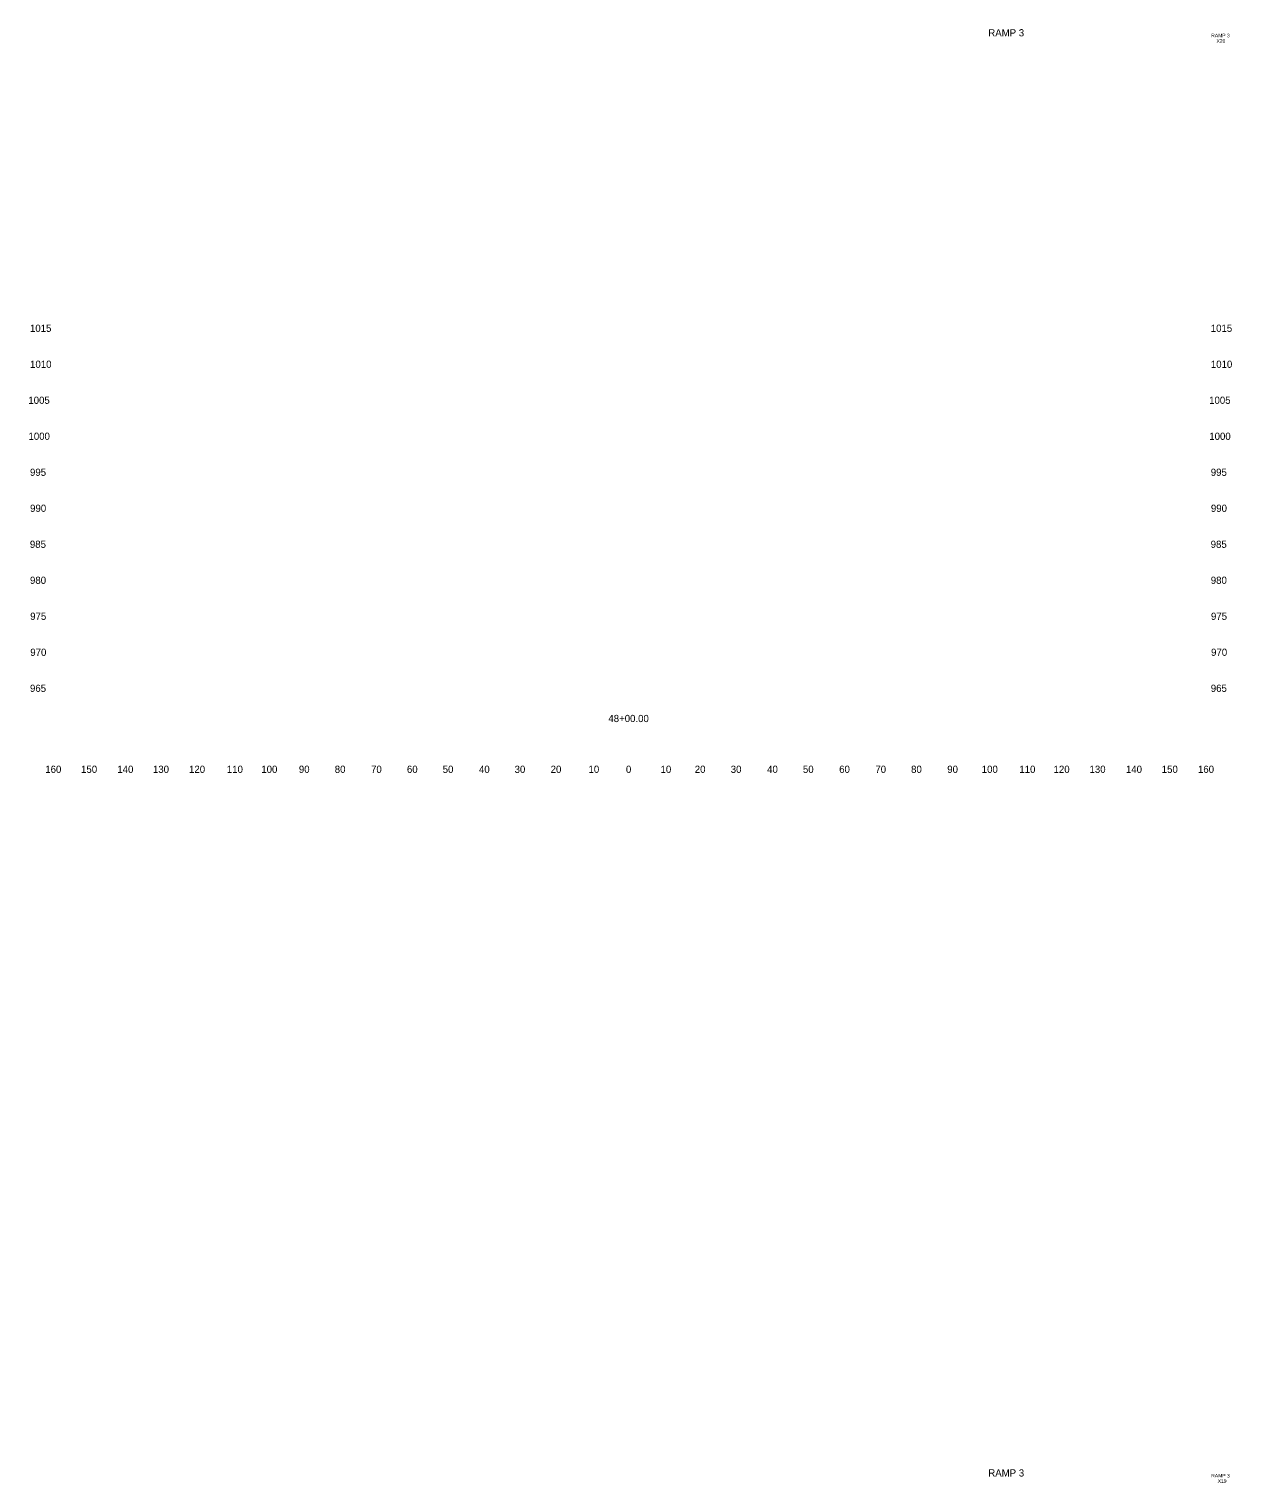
# Model space of a CAD drawing. Extents: x 4994 to 5843, y 4997 to 8804.
# Drawn here: x 5508.6 to 5842.5, y 8400.3 to 8804.1 of the extents above; entities that cross this region are included whole.
import ezdxf

# ---------------------------------------------------------------- set-up
doc = ezdxf.new("R2010")
doc.units = 0
for name, color, linetype in [('RD_SHT_ID', 7, 'Continuous'), ('RD_XS_TX_Offset', 7, 'Continuous'), ('RD_XS_TX_Station', 7, 'Continuous')]:
    doc.layers.add(name, color=color, linetype=linetype)

msp = doc.modelspace()

# ---------------------------------------------------------------- texts
at = {"layer": 'RD_SHT_ID'}
for s, height, p in [('RAMP 3', 2, (5774.89, 8802.06)), ('RAMP 3', 1, (5836.78, 8801.8)), ('X20', 1, (5838.25, 8800.3)), ('RAMP 3', 2, (5774.89, 8402.06)), ('RAMP 3', 1, (5836.78, 8401.8)), ('X19', 1, (5838.57, 8400.3))]:
    msp.add_text(s, height=height, dxfattribs=at).set_placement(p)
at = {"layer": 'RD_XS_TX_Offset'}
for s, p in [('1015', (5508.85, 8720)), ('1015', (5836.65, 8720)), ('1010', (5508.88, 8710)), ('1010', (5836.68, 8710)), ('1005', (5508.4, 8700)), ('1005', (5836.2, 8700)), ('1000', (5508.44, 8690)), ('1000', (5836.24, 8690)), ('995', (5508.86, 8680)), ('995', (5836.66, 8680)), ('990', (5508.89, 8670)), ('990', (5836.69, 8670)), ('985', (5508.83, 8660)), ('985', (5836.63, 8660)), ('980', (5508.86, 8650)), ('980', (5836.66, 8650)), ('975', (5508.91, 8640)), ('975', (5836.71, 8640)), ('970', (5508.94, 8630)), ('970', (5836.74, 8630)), ('965', (5508.86, 8620)), ('965', (5836.66, 8620)), ('160', (5513.1, 8597.5)), ('150', (5523.04, 8597.5)), ('140', (5533.1, 8597.5)), ('130', (5542.99, 8597.5)), ('120', (5553.01, 8597.5)), ('110', (5563.51, 8597.5)), ('100', (5573.07, 8597.5)), ('90', (5583.5, 8597.5)), ('80', (5593.46, 8597.5)), ('70', (5603.54, 8597.5)), ('60', (5613.5, 8597.5)), ('50', (5623.43, 8597.5)), ('40', (5633.5, 8597.5)), ('30', (5643.39, 8597.5)), ('20', (5653.4, 8597.5)), ('10', (5663.91, 8597.5)), ('0', (5674.3, 8597.5)), ('0', (5674.3, 8597.5)), ('10', (5683.91, 8597.5)), ('20', (5693.4, 8597.5)), ('30', (5703.39, 8597.5)), ('40', (5713.5, 8597.5)), ('50', (5723.43, 8597.5)), ('60', (5733.5, 8597.5)), ('70', (5743.54, 8597.5)), ('80', (5753.46, 8597.5)), ('90', (5763.5, 8597.5)), ('100', (5773.07, 8597.5)), ('110', (5783.51, 8597.5)), ('120', (5793.01, 8597.5)), ('130', (5802.99, 8597.5)), ('140', (5813.1, 8597.5)), ('150', (5823.04, 8597.5)), ('160', (5833.1, 8597.5))]:
    msp.add_text(s, height=2, dxfattribs=at).set_placement(p)
at = {"layer": 'RD_XS_TX_Station'}
msp.add_text('48+00.00', height=2, dxfattribs=at).set_placement((5669.42, 8611.61))

doc.saveas('drawing.dxf')
